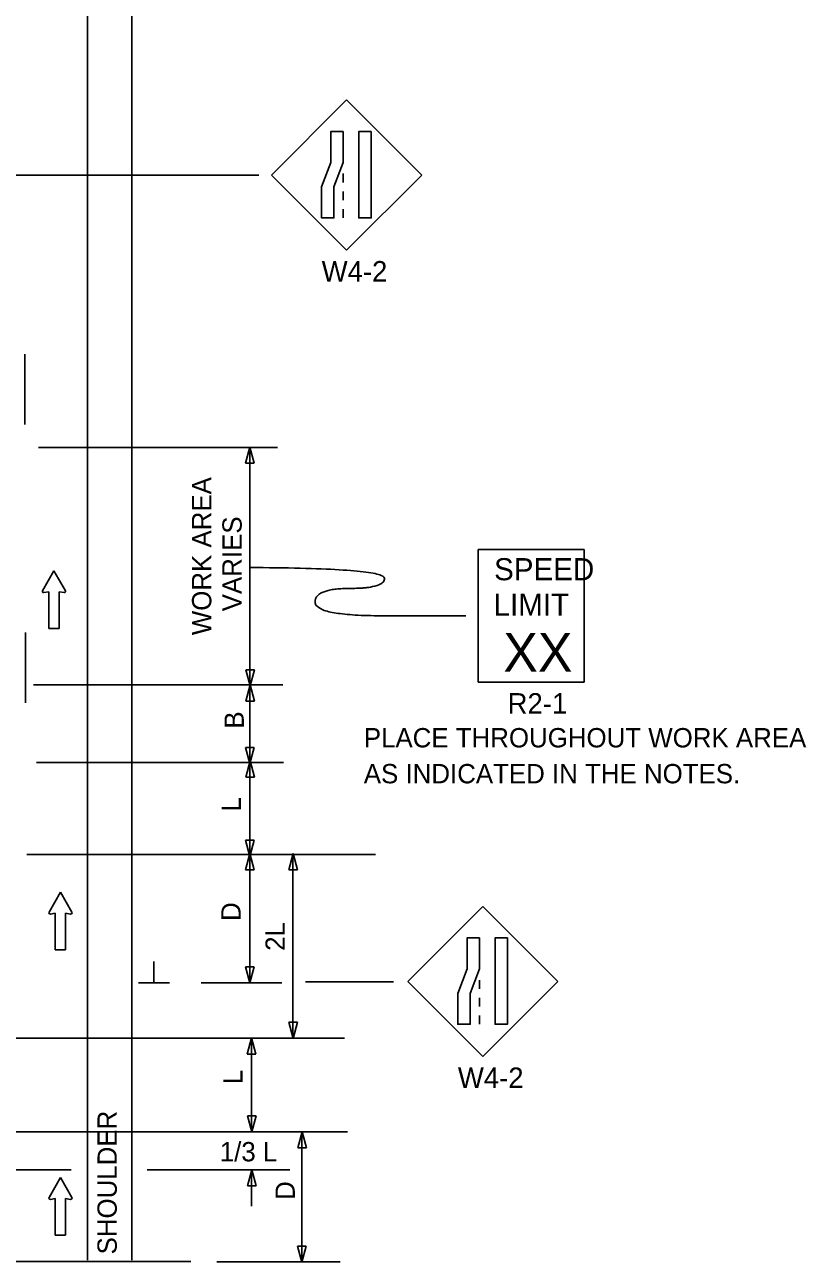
# Model space of a CAD drawing. Extents: x 20837 to 23689, y 414 to 2167.
# Drawn here: x 21274.7 to 21557.6, y 831.1 to 1279 of the extents above; entities that cross this region are included whole.
import ezdxf

# ---------------------------------------------------------------- set-up
doc = ezdxf.new("R2010")
doc.units = 0
for name, color, linetype in [('ALI_LEGAL_EX', 7, 'Continuous'), ('MT_SCRATCH_LEVEL_E', 7, 'Continuous'), ('PAVT_EDGE_EX', 7, 'Continuous'), ('TRAFFIC_SIGNS_PR', 7, 'Continuous'), ('TYPICAL_TEXT_DIMEN_PR', 7, 'Continuous')]:
    doc.layers.add(name, color=color, linetype=linetype)

msp = doc.modelspace()

# ---------------------------------------------------------------- linework, layer by layer
at = {"layer": 'ALI_LEGAL_EX'}
for points in [[(21274.69, 1134.35), (21274.69, 1159.87)], [(21274.98, 1033.66), (21274.98, 1059.07)]]:
    msp.add_lwpolyline(points, dxfattribs=at)
at = {"layer": 'MT_SCRATCH_LEVEL_E'}
for p, q in [((21285.23, 1081.44), (21281.12, 1074.2)), ((21285.23, 1081.44), (21281.12, 1074.2)), ((21289.38, 1074.2), (21285.23, 1081.44)), ((21289.38, 1074.2), (21285.23, 1081.44)), ((21281.6, 1073.52), (21283.38, 1073.83)), ((21281.6, 1073.52), (21283.38, 1073.83)), ((21283.38, 1073.83), (21283.38, 1060.57)), ((21283.38, 1073.83), (21283.38, 1060.57)), ((21287.12, 1060.57), (21287.12, 1073.83)), ((21287.12, 1073.83), (21288.9, 1073.52)), ((21287.12, 1060.57), (21287.12, 1073.83)), ((21287.12, 1073.83), (21288.9, 1073.52)), ((21283.38, 1060.57), (21287.12, 1060.57)), ((21283.38, 1060.57), (21287.12, 1060.57)), ((21287.59, 965.07), (21283.48, 957.83)), ((21287.59, 965.07), (21283.48, 957.83)), ((21291.74, 957.83), (21287.59, 965.07)), ((21291.74, 957.83), (21287.59, 965.07)), ((21283.96, 957.15), (21285.74, 957.46)), ((21283.96, 957.15), (21285.74, 957.46)), ((21285.74, 957.46), (21285.74, 944.21)), ((21285.74, 957.46), (21285.74, 944.21)), ((21289.48, 944.21), (21289.48, 957.46)), ((21289.48, 957.46), (21291.26, 957.15)), ((21289.48, 944.21), (21289.48, 957.46)), ((21289.48, 957.46), (21291.26, 957.15)), ((21285.74, 944.21), (21289.48, 944.21)), ((21285.74, 944.21), (21289.48, 944.21)), ((21287.59, 861.83), (21283.48, 854.59)), ((21287.59, 861.83), (21283.48, 854.59)), ((21291.74, 854.59), (21287.59, 861.83)), ((21291.74, 854.59), (21287.59, 861.83)), ((21283.96, 853.9), (21285.74, 854.22)), ((21283.96, 853.9), (21285.74, 854.22)), ((21285.74, 854.22), (21285.74, 840.96)), ((21285.74, 854.22), (21285.74, 840.96)), ((21289.48, 840.96), (21289.48, 854.22)), ((21289.48, 854.22), (21291.26, 853.9)), ((21289.48, 840.96), (21289.48, 854.22)), ((21289.48, 854.22), (21291.26, 853.9)), ((21285.74, 840.96), (21289.48, 840.96)), ((21285.74, 840.96), (21289.48, 840.96))]:
    msp.add_line(p, q, dxfattribs=at)
for centre, start, end in [((21281.53, 1073.98), 150.4248, 279.9638), ((21281.53, 1073.98), 150.4248, 279.9638), ((21288.97, 1073.98), 260.0362, 29.7731), ((21288.97, 1073.98), 260.0362, 29.7731), ((21283.89, 957.61), 150.4248, 279.9638), ((21283.89, 957.61), 150.4248, 279.9638), ((21291.33, 957.61), 260.0362, 29.7731), ((21291.33, 957.61), 260.0362, 29.7731), ((21283.89, 854.36), 150.4248, 279.9638), ((21283.89, 854.36), 150.4248, 279.9638), ((21291.33, 854.36), 260.0362, 29.7731), ((21291.33, 854.36), 260.0362, 29.7731)]:
    msp.add_arc(centre, 0.463, start, end, dxfattribs=at)
at = {"layer": 'PAVT_EDGE_EX'}
for p, q in [((21297.4, 1637.35), (21297.4, 831.94)), ((21313.4, 1636.75), (21313.4, 831.94))]:
    msp.add_line(p, q, dxfattribs=at)
at = {"layer": 'TRAFFIC_SIGNS_PR'}
for p, q in [((21391.2, 1251.81), (21364.05, 1224.66)), ((21418.36, 1224.66), (21391.2, 1251.81)), ((21364.05, 1224.66), (21391.2, 1197.51)), ((21389.96, 1225.15), (21389.96, 1221.95)), ((21391.2, 1197.51), (21418.36, 1224.66)), ((21389.96, 1218.75), (21389.96, 1215.55)), ((21389.96, 1212.35), (21389.96, 1209.15)), ((21438.8, 1089.12), (21477.2, 1089.12)), ((21438.8, 1041.12), (21438.8, 1089.12)), ((21477.2, 1041.12), (21477.2, 1089.12)), ((21438.8, 1041.12), (21477.2, 1041.12)), ((21440.52, 959.93), (21413.36, 932.78)), ((21467.67, 932.78), (21440.52, 959.93)), ((21413.36, 932.78), (21440.52, 905.62)), ((21439.27, 933.27), (21439.27, 930.07)), ((21440.52, 905.62), (21467.67, 932.78)), ((21439.27, 926.87), (21439.27, 923.67)), ((21439.27, 920.47), (21439.27, 917.27))]:
    msp.add_line(p, q, dxfattribs=at)
for points in [[(21389.96, 1240.4), (21389.96, 1229.21), (21386.61, 1220.33), (21386.61, 1209.15), (21382.12, 1209.15), (21382.12, 1220.33), (21385.46, 1229.21), (21385.46, 1240.4)], [(21400.09, 1240.4), (21400.09, 1209.15), (21395.6, 1209.15), (21395.6, 1240.4)], [(21439.27, 948.51), (21439.27, 937.33), (21435.92, 928.45), (21435.92, 917.27), (21431.43, 917.27), (21431.43, 928.45), (21434.78, 937.33), (21434.78, 948.51)], [(21449.4, 948.51), (21449.4, 917.27), (21444.91, 917.27), (21444.91, 948.51)]]:
    msp.add_lwpolyline(points, close=True, dxfattribs=at)
at = {"layer": 'TYPICAL_TEXT_DIMEN_PR'}
for p, q in [((21359.37, 1224.6), (21201.93, 1224.6)), ((21279.62, 1125.98), (21366.12, 1125.98)), ((21354.57, 1120.35), (21356.14, 1126.21)), ((21356.14, 1126.21), (21357.71, 1120.35)), ((21356.14, 1040.46), (21356.14, 1124.76)), ((21356.14, 1120.35), (21354.57, 1120.35)), ((21357.71, 1120.35), (21356.14, 1120.35)), ((21356.32, 1039.73), (21354.75, 1045.59)), ((21354.75, 1045.59), (21356.32, 1045.59)), ((21356.14, 932.65), (21356.14, 1044.65)), ((21356.32, 1045.59), (21357.89, 1045.59)), ((21357.89, 1045.59), (21356.32, 1039.73)), ((21368.04, 1040.07), (21277.85, 1040.07)), ((21354.75, 1034.21), (21356.32, 1040.07)), ((21356.32, 1040.07), (21357.89, 1034.21)), ((21356.32, 1034.21), (21354.75, 1034.21)), ((21357.89, 1034.21), (21356.32, 1034.21)), ((21356.14, 1011.6), (21354.57, 1017.46)), ((21354.57, 1017.46), (21356.14, 1017.46)), ((21356.14, 1017.46), (21357.71, 1017.46)), ((21357.71, 1017.46), (21356.14, 1011.6)), ((21354.75, 1006.75), (21356.32, 1012.62)), ((21356.32, 1012.62), (21357.89, 1006.75)), ((21368.3, 1011.99), (21278.93, 1011.99)), ((21356.32, 1006.75), (21354.75, 1006.75)), ((21357.89, 1006.75), (21356.32, 1006.75)), ((21356.14, 978.05), (21354.57, 983.91)), ((21354.57, 983.91), (21356.14, 983.91)), ((21356.14, 983.91), (21357.71, 983.91)), ((21357.71, 983.91), (21356.14, 978.05)), ((21401.6, 978.77), (21275.45, 978.77)), ((21354.57, 973.2), (21356.14, 979.06)), ((21356.14, 979.06), (21357.71, 973.2)), ((21370.25, 973.17), (21371.82, 979.03)), ((21371.75, 978.5), (21371.75, 912.32)), ((21371.82, 979.03), (21373.39, 973.17)), ((21356.14, 973.2), (21354.57, 973.2)), ((21357.71, 973.2), (21356.14, 973.2)), ((21371.82, 973.17), (21370.25, 973.17)), ((21373.39, 973.17), (21371.82, 973.17)), ((21321.45, 932.21), (21321.45, 940)), ((21356.14, 932.25), (21354.57, 938.11)), ((21354.57, 938.11), (21356.14, 938.11)), ((21356.14, 938.11), (21357.71, 938.11)), ((21357.71, 938.11), (21356.14, 932.25)), ((21327.08, 932.21), (21315.83, 932.21)), ((21367.69, 932.25), (21338.49, 932.25)), ((21408.2, 932.59), (21376.28, 932.59)), ((21371.83, 912.13), (21370.26, 917.99)), ((21370.26, 917.99), (21371.83, 917.99)), ((21371.83, 917.99), (21373.4, 917.99)), ((21373.4, 917.99), (21371.83, 912.13)), ((21390.41, 912.25), (21257.22, 912.25)), ((21355.23, 906.49), (21356.8, 912.35)), ((21356.72, 911.94), (21356.72, 878.55)), ((21356.8, 912.35), (21358.37, 906.49)), ((21356.8, 906.49), (21355.23, 906.49)), ((21358.37, 906.49), (21356.8, 906.49)), ((21356.85, 878.32), (21355.28, 884.18)), ((21355.28, 884.18), (21356.85, 884.18)), ((21356.85, 884.18), (21358.42, 884.18)), ((21358.42, 884.18), (21356.85, 878.32)), ((21391.49, 878.35), (21236.08, 878.35)), ((21373.51, 872.49), (21375.08, 878.35)), ((21375.01, 831.57), (21375.01, 877.91)), ((21375.08, 878.35), (21376.65, 872.49)), ((21375.08, 872.49), (21373.51, 872.49)), ((21376.65, 872.49), (21375.08, 872.49)), ((21291.52, 864.6), (21208.33, 864.6)), ((21370.6, 864.6), (21319.04, 864.6)), ((21355.28, 858.74), (21356.85, 864.6)), ((21356.85, 864.6), (21358.42, 858.74)), ((21356.78, 864.45), (21356.78, 851.46)), ((21356.85, 858.74), (21355.28, 858.74)), ((21358.42, 858.74), (21356.85, 858.74)), ((21375.03, 831.13), (21373.46, 837)), ((21373.46, 837), (21375.03, 837)), ((21375.03, 837), (21376.6, 837)), ((21376.6, 837), (21375.03, 831.13)), ((21088.66, 831.41), (21334.82, 831.41)), ((21388.83, 831.26), (21344.16, 831.26))]:
    msp.add_line(p, q, dxfattribs=at)
msp.add_open_spline([(21356.14, 1082.61), (21404.94, 1082.29), (21404.94, 1075.03), (21379.76, 1075.03), (21379.76, 1065.12), (21429.41, 1065.12), (21434.34, 1065.12)], degree=2, dxfattribs=at)

# ---------------------------------------------------------------- texts
at = {"layer": 'TRAFFIC_SIGNS_PR'}
for s, height, p in [('W4-2', 7.44, (21382.16, 1186.07)), ('SPEED', 8, (21444.57, 1077.98)), ('LIMIT', 8, (21444.41, 1065.18)), ('XX', 14.031, (21447.91, 1044.88)), ('R2-1', 7.44, (21449.48, 1029.68)), ('PLACE THROUGHOUT WORK AREA', 7, (21397.41, 1017.48)), ('AS INDICATED IN THE NOTES.', 7, (21397.41, 1004.48)), ('W4-2', 7.44, (21431.47, 894.19))]:
    msp.add_text(s, height=height, dxfattribs=at).set_placement(p)
at = {"layer": 'TYPICAL_TEXT_DIMEN_PR'}
for s, p in [('WORK AREA', (21342.22, 1058.1)), ('VARIES', (21353.22, 1066.74)), ('B', (21353.99, 1024.27)), ('L', (21352.92, 994.27)), ('D', (21352.82, 954.66)), ('2L', (21368.82, 943.84)), ('L', (21353.52, 895.57)), ('SHOULDER', (21307.99, 833.96)), ('D', (21372.45, 853.7))]:
    msp.add_text(s, height=7, rotation=90, dxfattribs=at).set_placement(p)
msp.add_text('1/3 L', height=7, dxfattribs=at).set_placement((21345.28, 867.65))

doc.saveas('drawing.dxf')
